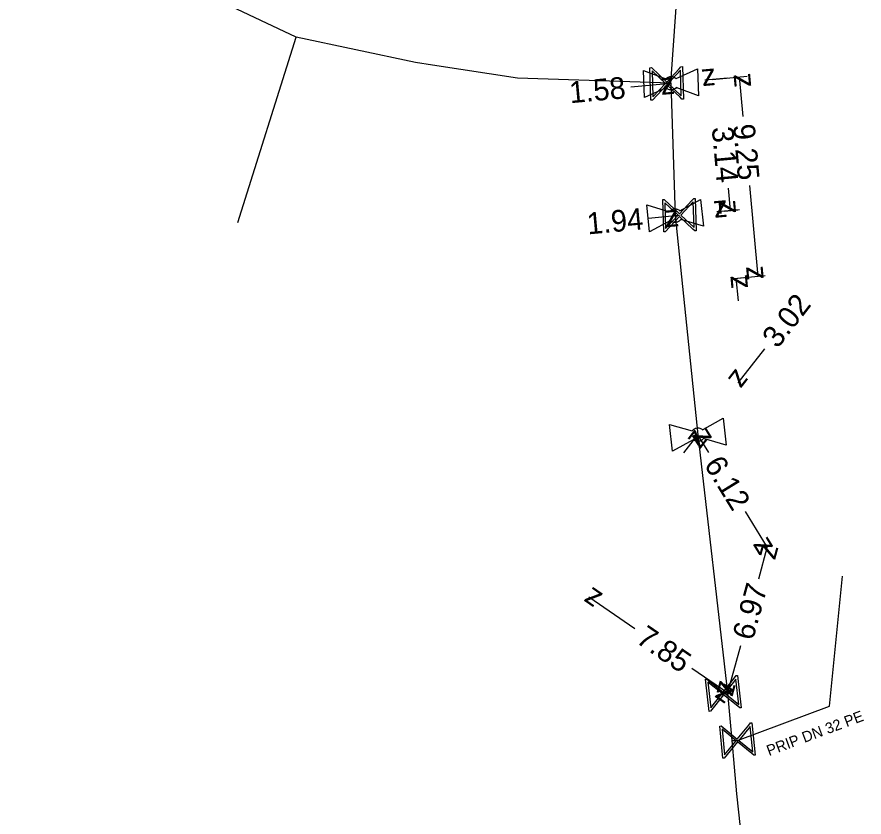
# Model space of a CAD drawing. Extents: x -638315 to -636370, y -1116147 to -1115110.
# Drawn here: x -637124.46 to -637085.31, y -1115989.16 to -1115952.2 of the extents above; entities that cross this region are included whole.
import ezdxf

# ---------------------------------------------------------------- set-up
doc = ezdxf.new("R2010")
doc.units = 0
for name, color, linetype in [('Default', 7, 'Continuous'), ('VP Kótování', 7, 'Continuous'), ('VP Lomový bod', 7, 'Continuous'), ('VP Popis přípojky', 7, 'Continuous'), ('VP Přípojka', 7, 'Continuous'), ('VP Řad', 7, 'Continuous'), ('VP Šoupě', 7, 'Continuous')]:
    doc.layers.add(name, color=color, linetype=linetype)

msp = doc.modelspace()

# ---------------------------------------------------------------- linework, layer by layer
at = {"layer": 'Default'}
for points in [[(-637094.473, -1115955.066), (-637094.44, -1115955.025), (-637094.393, -1115954.996), (-637094.321, -1115954.953), (-637094.239, -1115954.95), (-637094.158, -1115954.947), (-637094.081, -1115954.988), (-637094.033, -1115955.012), (-637093.998, -1115955.051)], [(-637093.985, -1115955.46), (-637094.018, -1115955.5), (-637094.064, -1115955.528), (-637094.138, -1115955.572), (-637094.22, -1115955.575), (-637094.302, -1115955.577), (-637094.376, -1115955.538), (-637094.425, -1115955.513), (-637094.46, -1115955.474)], [(-637094.295, -1115961.201), (-637094.266, -1115961.158), (-637094.221, -1115961.126), (-637094.152, -1115961.077), (-637094.071, -1115961.069), (-637093.99, -1115961.06), (-637093.91, -1115961.095), (-637093.861, -1115961.116), (-637093.823, -1115961.152)], [(-637093.781, -1115961.559), (-637093.811, -1115961.601), (-637093.854, -1115961.633), (-637093.925, -1115961.682), (-637094.007, -1115961.69), (-637094.088, -1115961.699), (-637094.165, -1115961.665), (-637094.215, -1115961.643), (-637094.253, -1115961.607)], [(-637093.249, -1115971.324), (-637093.219, -1115971.28), (-637093.175, -1115971.248), (-637093.107, -1115971.198), (-637093.026, -1115971.189), (-637092.945, -1115971.18), (-637092.864, -1115971.213), (-637092.815, -1115971.234), (-637092.777, -1115971.27)], [(-637092.73, -1115971.676), (-637092.759, -1115971.719), (-637092.803, -1115971.751), (-637092.873, -1115971.801), (-637092.954, -1115971.81), (-637093.035, -1115971.819), (-637093.113, -1115971.786), (-637093.163, -1115971.765), (-637093.202, -1115971.729)]]:
    msp.add_open_spline(points, degree=3, dxfattribs=at)
at = {"layer": 'VP Kótování'}
for points in [[(-637091.615, -1115955.024), (-637092.661, -1115955.119)], [(-637092.312, -1115955.087), (-637090.714, -1115954.941)], [(-637090.897, -1115956.792), (-637091.063, -1115954.973)], [(-637096.083, -1115955.431), (-637094.23, -1115955.262)], [(-637091.59, -1115960.107), (-637091.496, -1115961.147)], [(-637090.605, -1115959.989), (-637090.222, -1115964.184)], [(-637095.27, -1115961.491), (-637094.039, -1115961.379)], [(-637091.059, -1115961.108), (-637092.105, -1115961.203)], [(-637091.756, -1115961.171), (-637091.147, -1115961.116)], [(-637091.471, -1115964.298), (-637089.873, -1115964.152)], [(-637091.471, -1115964.298), (-637090.862, -1115964.243)], [(-637091.115, -1115965.32), (-637091.211, -1115964.274)], [(-637089.914, -1115967.526), (-637091.14, -1115969.11)], [(-637093.633, -1115972.33), (-637092.99, -1115971.5)], [(-637092.487, -1115972.317), (-637092.99, -1115971.5)], [(-637090.804, -1115975.048), (-637089.78, -1115976.71)], [(-637090.175, -1115978.156), (-637089.78, -1115976.71)], [(-637095.907, -1115980.462), (-637098.03, -1115979)], [(-637091.019, -1115981.251), (-637091.614, -1115983.43)], [(-637093.262, -1115982.282), (-637091.562, -1115983.453)]]:
    msp.add_lwpolyline(points, dxfattribs=at)
at = {"layer": 'VP Lomový bod'}
for points in [[(-637094.46, -1115955.474), (-637095.459, -1115955.926), (-637095.498, -1115954.677), (-637094.473, -1115955.066)], [(-637093.998, -1115955.051), (-637093, -1115954.599)], [(-637093, -1115954.599), (-637092.961, -1115955.848), (-637093.985, -1115955.46)], [(-637093.823, -1115961.152), (-637092.86, -1115960.629)], [(-637092.86, -1115960.629), (-637092.731, -1115961.872), (-637093.781, -1115961.559)], [(-637094.253, -1115961.607), (-637095.218, -1115962.13), (-637095.347, -1115960.887), (-637094.295, -1115961.201)], [(-637092.777, -1115971.27), (-637091.82, -1115970.735)], [(-637091.82, -1115970.735), (-637091.677, -1115971.977), (-637092.73, -1115971.676)], [(-637093.202, -1115971.729), (-637094.16, -1115972.264), (-637094.303, -1115971.022), (-637093.249, -1115971.324)]]:
    msp.add_lwpolyline(points, dxfattribs=at)
at = {"layer": 'VP Přípojka'}
for points in [[(-637114.255, -1115961.69), (-637111.55, -1115953.13)], [(-637094.43, -1115955.27), (-637094.23, -1115955.262)], [(-637094.039, -1115961.379), (-637093.84, -1115961.36)], [(-637091.423, -1115985.63), (-637091.36, -1115985.63), (-637091.16, -1115985.63), (-637086.91, -1115984.04), (-637086.31, -1115978.04)], [(-637091.614, -1115983.43), (-637091.812, -1115983.453)]]:
    msp.add_lwpolyline(points, dxfattribs=at)
at = {"layer": 'VP Řad'}
for points in [[(-637094.23, -1115955.262), (-637101.32, -1115955.03), (-637105.251, -1115954.422), (-637106.04, -1115954.3), (-637111.55, -1115953.13), (-637115.37, -1115951.32), (-637118.85, -1115948.77), (-637122.11, -1115946.05), (-637124.84, -1115943.56), (-637126.75, -1115941.96), (-637130.14, -1115939.39), (-637130.41, -1115939.26), (-637130.63, -1115939.07), (-637131.29, -1115938.52), (-637131.65, -1115938.26)], [(-637094.23, -1115955.262), (-637093.49, -1115944.54)], [(-637094.23, -1115955.262), (-637094.039, -1115961.379), (-637092.99, -1115971.5), (-637091.614, -1115983.43), (-637091.423, -1115985.63), (-637091.203, -1115988.085), (-637090.958, -1115990.36), (-637090.777, -1115992.041), (-637090.17, -1115997.67), (-637089.75, -1116008.07), (-637090.11, -1116022.496)]]:
    msp.add_lwpolyline(points, dxfattribs=at)
at = {"layer": 'VP Šoupě'}
for points in [[(-637093.704, -1115954.497), (-637093.657, -1115955.996), (-637093.723, -1115955.998), (-637093.813, -1115955.907), (-637094.426, -1115955.333), (-637095.09, -1115956.041), (-637095.156, -1115956.043), (-637095.203, -1115954.544), (-637095.137, -1115954.542), (-637094.43, -1115955.208), (-637093.856, -1115954.595), (-637093.769, -1115954.499), (-637093.704, -1115954.497)], [(-637095.067, -1115955.888), (-637094.491, -1115955.273), (-637095.104, -1115954.697), (-637095.067, -1115955.888)], [(-637093.792, -1115954.657), (-637094.366, -1115955.269), (-637093.755, -1115955.841), (-637093.792, -1115954.657)], [(-637093.114, -1115960.587), (-637093.067, -1115962.086), (-637093.133, -1115962.088), (-637093.223, -1115961.997), (-637093.836, -1115961.423), (-637094.5, -1115962.131), (-637094.566, -1115962.133), (-637094.613, -1115960.634), (-637094.547, -1115960.632), (-637093.84, -1115961.298), (-637093.266, -1115960.685), (-637093.179, -1115960.589), (-637093.114, -1115960.587)], [(-637094.477, -1115961.978), (-637093.901, -1115961.363), (-637094.514, -1115960.787), (-637094.477, -1115961.978)], [(-637093.202, -1115960.747), (-637093.776, -1115961.359), (-637093.165, -1115961.931), (-637093.202, -1115960.747)], [(-637091.153, -1115982.622), (-637090.981, -1115984.112), (-637091.046, -1115984.12), (-637091.144, -1115984.037), (-637091.803, -1115983.515), (-637092.406, -1115984.276), (-637092.471, -1115984.284), (-637092.643, -1115982.794), (-637092.577, -1115982.786), (-637091.817, -1115983.392), (-637091.296, -1115982.733), (-637091.218, -1115982.63), (-637091.153, -1115982.622)], [(-637092.395, -1115984.122), (-637091.872, -1115983.461), (-637092.532, -1115982.939), (-637092.395, -1115984.122)], [(-637091.228, -1115982.789), (-637091.749, -1115983.446), (-637091.092, -1115983.966), (-637091.228, -1115982.789)], [(-637090.487, -1115984.81), (-637090.34, -1115986.303), (-637090.406, -1115986.309), (-637090.502, -1115986.225), (-637091.152, -1115985.693), (-637091.767, -1115986.444), (-637091.833, -1115986.45), (-637091.98, -1115984.957), (-637091.914, -1115984.951), (-637091.165, -1115985.569), (-637090.633, -1115984.919), (-637090.553, -1115984.817), (-637090.487, -1115984.81)], [(-637091.755, -1115986.289), (-637091.221, -1115985.637), (-637091.871, -1115985.104), (-637091.755, -1115986.289)], [(-637090.565, -1115984.976), (-637091.097, -1115985.625), (-637090.449, -1115986.155), (-637090.565, -1115984.976)]]:
    msp.add_lwpolyline(points, dxfattribs=at)

# ---------------------------------------------------------------- texts
at = {"layer": 'VP Kótování'}
for s, rotation, p in [('z', 185.2076, (-637092.208, -1115954.576)), ('1.58', 5.2076, (-637098.884, -1115956.188)), ('z', 5.2076, (-637094.683, -1115955.805)), ('z', 95.2169, (-637090.519, -1115955.426)), ('3.14', 275.2077, (-637092.348, -1115957.306)), ('9.25', 275.2168, (-637091.363, -1115957.186)), ('z', 185.1997, (-637091.652, -1115960.66)), ('z', 275.2076, (-637092.039, -1115960.695)), ('1.94', 5.1998, (-637098.071, -1115962.248)), ('z', 5.1998, (-637094.492, -1115961.922)), ('z', 275.2169, (-637090.765, -1115963.732)), ('z', 95.2077, (-637090.667, -1115964.727)), ('3.02', 52.258, (-637089.304, -1115967.555)), ('z', 232.258, (-637091.229, -1115968.409)), ('z', 121.6382, (-637092.302, -1115971.663)), ('z', 52.258, (-637092.901, -1115972.201)), ('6.12', 301.6382, (-637092.729, -1115972.877)), ('z', 301.6382, (-637090.468, -1115976.547)), ('z', 74.7348, (-637089.429, -1115977.324)), ('z', 145.4539, (-637097.335, -1115978.872)), ('6.97', 74.7348, (-637090.445, -1115981.045)), ('7.85', 325.4539, (-637095.902, -1115981.072)), ('z', 254.7348, (-637091.965, -1115982.816)), ('z', 325.4539, (-637092.257, -1115983.581))]:
    msp.add_text(s, height=1, rotation=rotation, dxfattribs=at).set_placement(p)
at = {"layer": 'VP Popis přípojky'}
msp.add_text('PRIP DN 32 PE', height=0.5, rotation=20.5117, dxfattribs=at).set_placement((-637089.701, -1115986.351))

doc.saveas('drawing.dxf')
